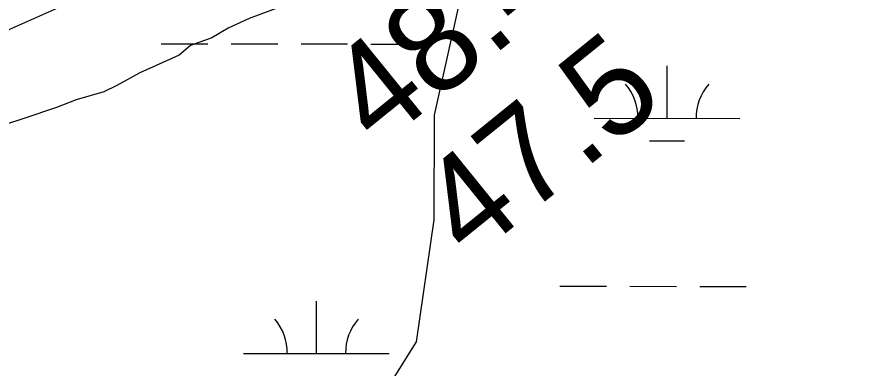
# Model space of a CAD drawing. Extents: x 3208593 to 3246461, y 812903 to 838290.
# Drawn here: x 3213953 to 3214527, y 828709 to 828950 of the extents above; entities that cross this region are included whole.
import ezdxf

# ---------------------------------------------------------------- set-up
doc = ezdxf.new("R2010")
doc.units = 0
for name, color, linetype in [('V-RIVR-RANG', 7, 'Continuous'), ('V-SITE-VEGE', 7, 'Continuous'), ('V-TOPO-SHOR', 7, 'Continuous'), ('V-WETL-SWMP', 7, 'Continuous')]:
    doc.layers.add(name, color=color, linetype=linetype)

msp = doc.modelspace()

# ---------------------------------------------------------------- linework, layer by layer
at = {"layer": 'V-SITE-VEGE'}
for p, q in [((3214133.28, 828956.52), (3214113.12, 828948.92)), ((3214113.12, 828948.92), (3214098.55, 828942.37)), ((3214098.55, 828942.37), (3214087.32, 828935.8)), ((3214087.32, 828935.8), (3214072.76, 828930.36)), ((3214072.76, 828930.36), (3214064.88, 828923.75)), ((3214064.88, 828923.75), (3214037.98, 828911.75)), ((3214037.98, 828911.75), (3214022.27, 828902.99)), ((3214013.3, 828898.61), (3213994.28, 828893.23)), ((3214022.27, 828902.99), (3214013.3, 828898.61)), ((3213994.28, 828893.23), (3213980.83, 828887.79)), ((3213980.83, 828887.79), (3213958.44, 828880.21)), ((3213958.44, 828880.21), (3213945.01, 828875.88))]:
    msp.add_line(p, q, dxfattribs=at)
at = {"layer": 'V-TOPO-SHOR'}
msp.add_lwpolyline([(3213759.23, 827996.08), (3213747.34, 828068.05), (3213759.47, 828163.96), (3213855.59, 828295.72), (3213963.65, 828391.49), (3214035.64, 828427.36), (3214095.74, 828523.2), (3214167.84, 828631.01), (3214227.94, 828726.85), (3214240.05, 828810.77), (3214240.15, 828882.72), (3214264.29, 828990.6), (3214348.4, 829110.39), (3214396.47, 829182.26), (3214492.56, 829290.04), (3214576.58, 829349.87)], dxfattribs=at)
at = {"layer": 'V-WETL-SWMP'}
for p, q in [((3214141.13, 829027.39), (3213925.14, 828931.07)), ((3214052.63, 828931.69), (3214084.63, 828931.64)), ((3214100.63, 828931.62), (3214132.63, 828931.57)), ((3214148.63, 828931.55), (3214180.63, 828931.5)), ((3214196.63, 828931.48), (3214228.63, 828931.43)), ((3214399.88, 828880.44), (3214399.93, 828916.44)), ((3214349.88, 828880.51), (3214449.88, 828880.37)), ((3214387.85, 828865.03), (3214411.85, 828864.99)), ((3214326.3, 828765.11), (3214358.3, 828765.07)), ((3214374.3, 828765.04), (3214406.3, 828765)), ((3214422.3, 828764.97), (3214454.3, 828764.93)), ((3214159.17, 828718.93), (3214159.22, 828754.93)), ((3214109.17, 828719), (3214209.17, 828718.85))]:
    msp.add_line(p, q, dxfattribs=at)
for centre, start, end in [((3214344.63, 828880.99), 359.14484, 40.6885), ((3214455.12, 828880.83), 139.14483, 180.68849), ((3214103.93, 828719.48), 359.14484, 40.6885), ((3214214.41, 828719.32), 139.14483, 180.68849)]:
    msp.add_arc(centre, 35.25, start, end, dxfattribs=at)

# ---------------------------------------------------------------- texts
at = {"layer": 'V-RIVR-RANG'}
for s, p in [('48.4', (3214201.78, 828859.41)), ('47.5', (3214264.88, 828781.84))]:
    msp.add_text(s, height=67, rotation=38.98833, dxfattribs=at).set_placement(p)

doc.saveas('drawing.dxf')
